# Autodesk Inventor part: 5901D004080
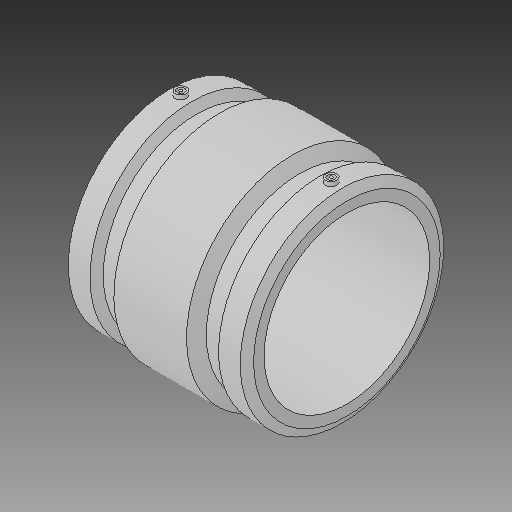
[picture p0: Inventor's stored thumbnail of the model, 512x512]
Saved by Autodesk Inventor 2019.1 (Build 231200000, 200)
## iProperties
Created: 2017-06
Part Number: 5901D004080
Material: Generic
Description: PLASSON COUPLER 8''DIPS
Document SubType Name: Modeling
Designer: KIM
Mass: 96874 g
Surface Area: 34549.7 cm^2
Volume: 96874 cm^3
Density: 1 g/cm^3
Appearance: Default
Author: KIM
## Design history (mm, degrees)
derived "5901D.ipt"
feature "Solid1::5901D.ipt"
tag "TaggingFeature1"
body "Solid1"
other parameters: "d13" = 240.03, "d15" = 118.618, "d16" = 118.618, "d17" = 218.7, "d22" = 279.908, "d23" = 279.4, "d24" = 246.31904, "d25" = 150 deg, "d26" = 96.012, "d27" = 120 deg, "d29" = 139.954, "d35" = 15, "d39" = 0, "d40" = 4, "d41" = 14, "d42" = 0, "d44" = 41.5163, "d45" = 218.7, "d47" = 0, "d48" = 134.35584, "d49" = 41.5163, "d50" = 60 deg, "d57" = 65.786, "d58" = 41.5163, "d62" = 218.7, "d65" = 282.448, "d67" = 5.27613, "d68" = 21.15863, "d69" = 21.80789, "d70" = 21.71015, "d71" = 20.5722, "d72" = 20.71531, "d73" = 561.2638, "d76" = 96.012, "d77" = 246.31904, "d_" = 218.7, "L_" = 240.03, "L_1" = 118.618, "D_" = 279.4, "A_" = 139.954, "A_1" = 25.4, "d60" = 187.96
